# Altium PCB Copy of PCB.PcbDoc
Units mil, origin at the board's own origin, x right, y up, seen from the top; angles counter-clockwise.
Board outline 1574.8 x 1496.06 mil, 2 copper layers (Top Layer, Bottom Layer); 38 components, 67 nets, 271 pads, 68 vias.
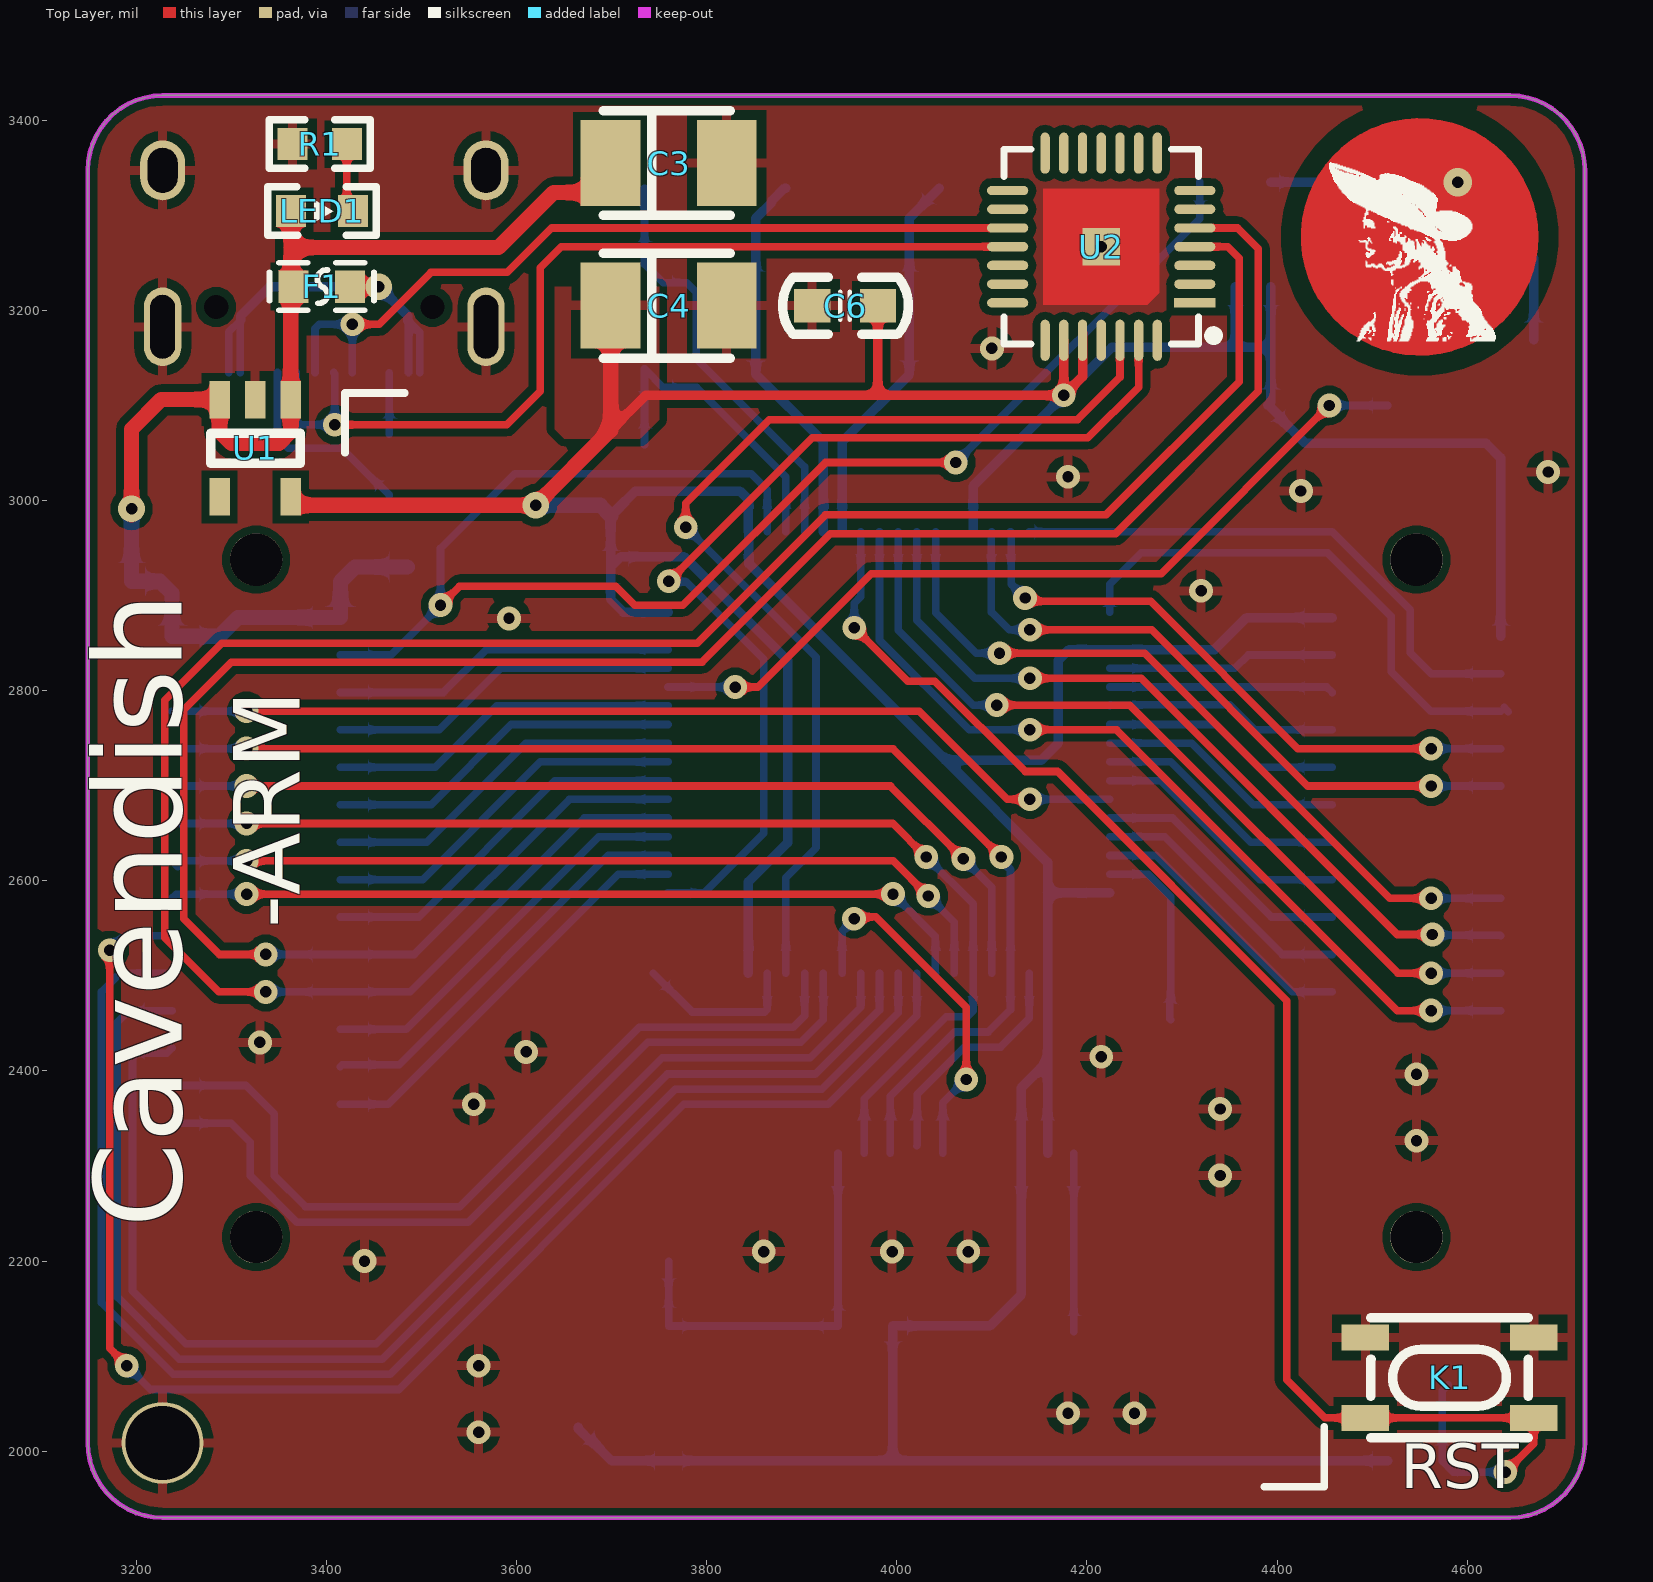
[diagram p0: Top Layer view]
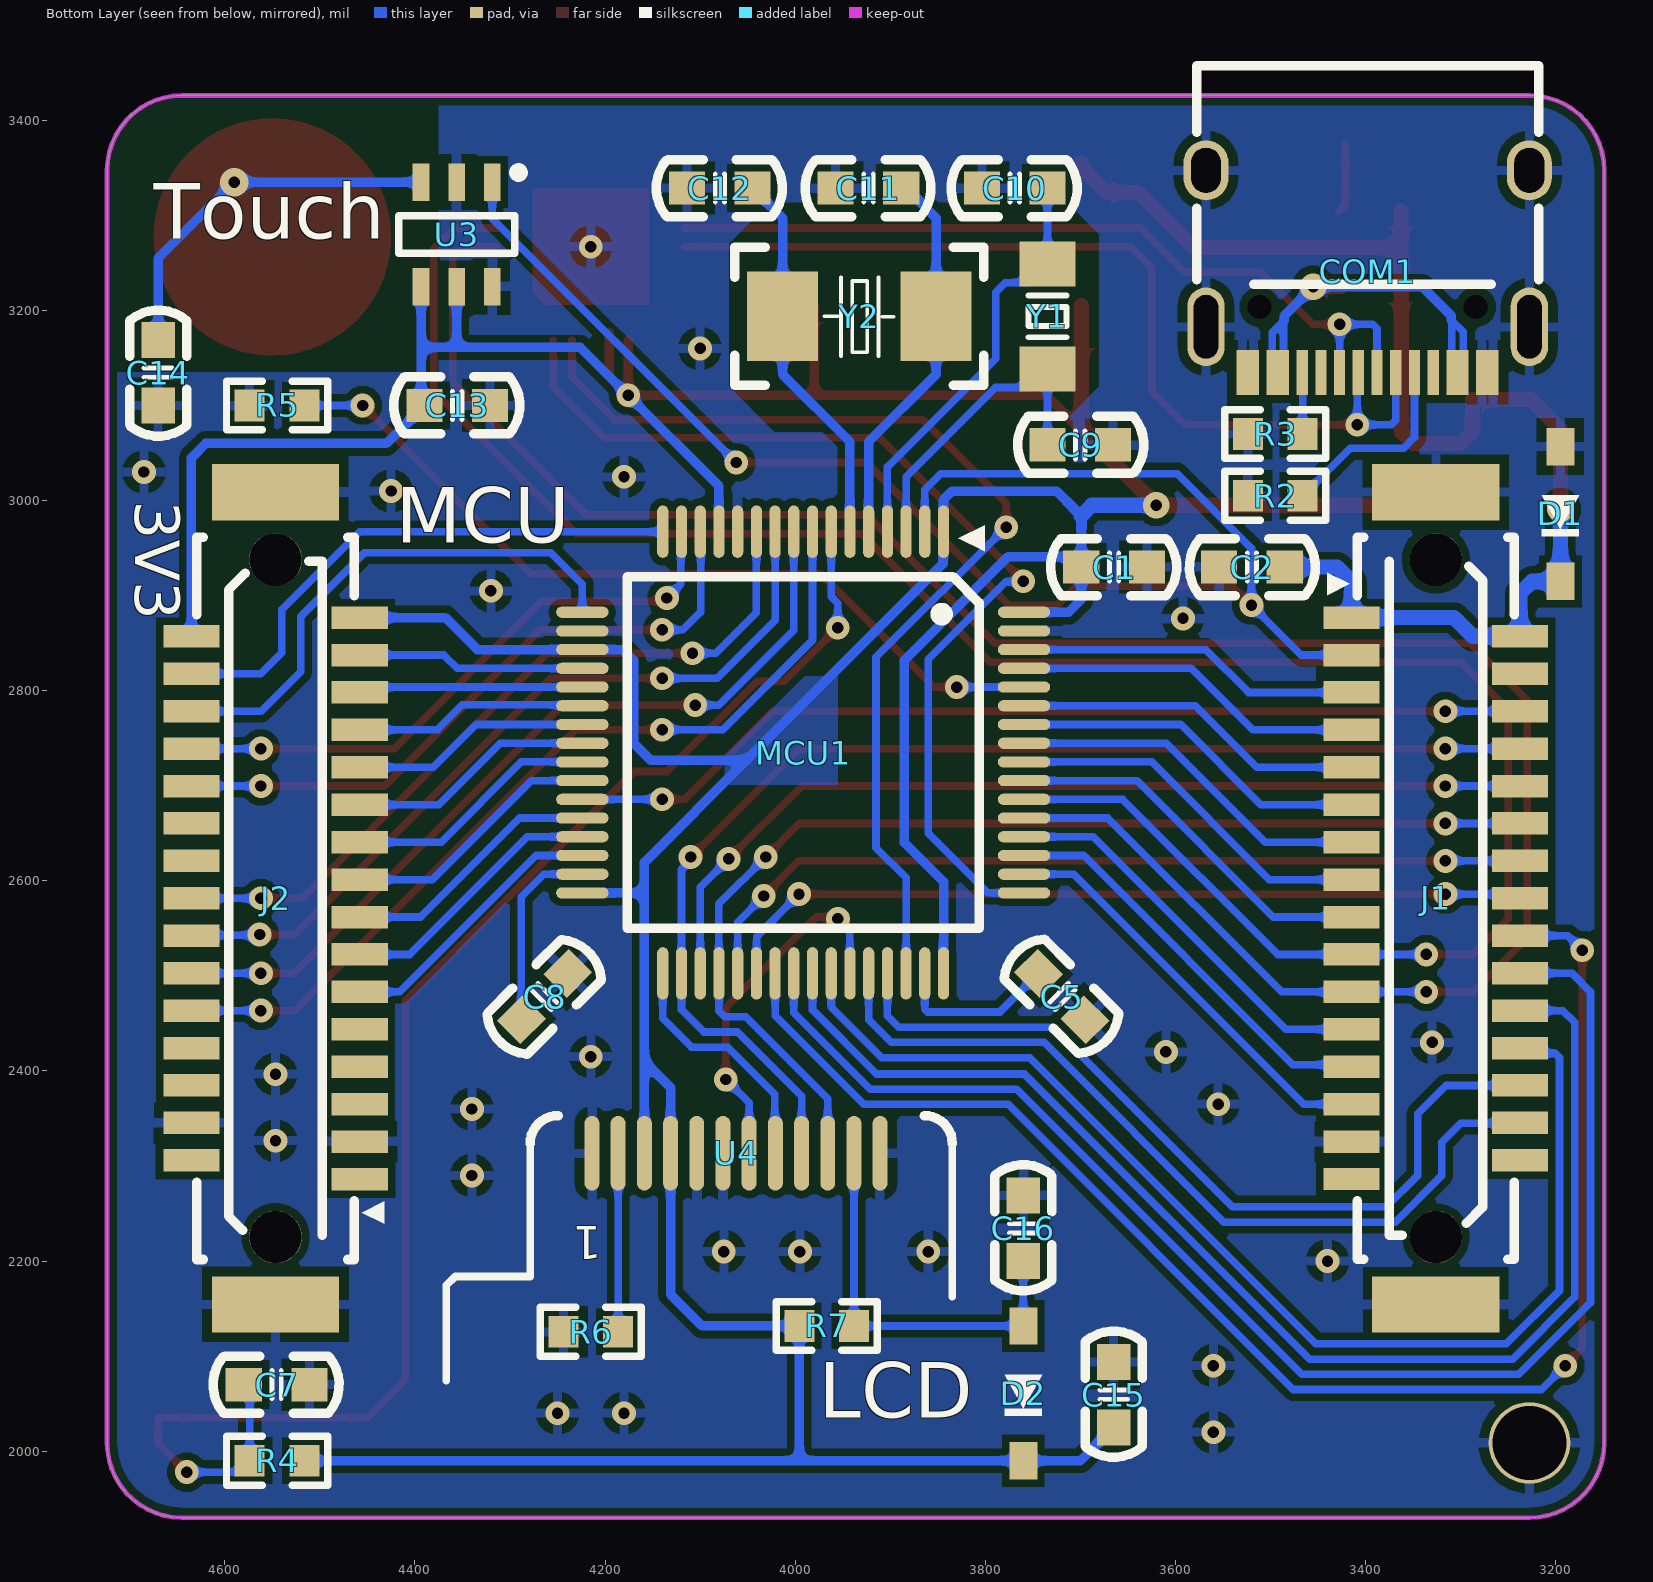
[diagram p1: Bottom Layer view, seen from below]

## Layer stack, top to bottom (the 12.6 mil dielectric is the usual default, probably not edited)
Top Solder: solder mask 0.4, Solder Resist, Dk 3.5
Top Layer: signal copper 1.4
Dielectric 1: dielectric 12.6, FR-4, Dk 4.8
Bottom Layer: signal copper 1.4
Bottom Solder: solder mask 0.4, Solder Resist, Dk 3.5

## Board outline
3148.94,2008.74 ccw(c3227.68,2008.74) 3227.68,1930 4645,1930 ccw(c4645,2008.74) 4723.74,2008.74 4723.74,3347.32 ccw(c4645,3347.32) 4645,3426.06 3260.17,3426.06 3227.68,3426.06 ccw(c3227.68,3347.32) 3148.94,3347.32

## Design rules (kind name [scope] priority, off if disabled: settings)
Clearance [All] p1: gap=8 ignorepadtopadclearanceinfootprint=TRUE
HoleSize [All] p1: absolutevalues=TRUE maxlimit=400 minlimit=1 maxpercent=80.000 minpercent=20.000
HoleToHoleClearance [All] p1: gap=6 allowstackedmicrovias=TRUE
MinimumSolderMaskSliver [All] p1: minsoldermaskwidth=1
PolygonConnect [All] p1: connectstyle=Relief reliefconductorwidth=10 reliefentries=4 polygonreliefangle="90 Angle" airgapwidth=10
RoutingVias [All] p1: holewidth=28 width=50 viastyle="Through Hole" minholewidth=12 minwidth=16 maxholewidth=28 maxwidth=50
SilkToSilkClearance [All] p1: silktosilkclearance=0
SilkToSolderMaskClearance [IsPad] p1: minsilkscreentomaskgap=0 clearancetoexposedcopper=TRUE
SolderMaskExpansion [All] p1: expansion=4 istentingtop=FALSE
Width [All] p1: maxlimit=50 minlimit=8 preferedwidth=10
25 further rules are at their usual default settings.

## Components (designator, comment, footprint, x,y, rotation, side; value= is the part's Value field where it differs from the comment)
C1 "100NF" CAP_0603 3630,2930 r0 bottom
C2 "100NF" CAP_0603 3554,2930 r180 bottom
C3 "22UF" CAP_3528_B 3760,3355 r180 top
C4 "22UF" CAP_3528_B 3760,3205 r180 top
C5 "10UF" CAP_0603 3695.16,2453.83 r45 bottom
C6 "100NF" CAP_0603 3911,3205 r0 top
C7 "100NF" CAP_0603 4511,2070 r0 bottom
C8 "10UF" CAP_0603 4239.22,2502.62 r315 bottom
C9 "10PF" CAP_0603 3734.62,3058.59 r180 bottom
C10 "10PF" CAP_0603 3734.62,3328.63 r0 bottom
C11 "22PF" CAP_0603 3888.37,3328.63 r0 bottom
C12 "22PF" CAP_0603 4044.77,3328.63 r0 bottom
C13 "100NF" CAP_0603 4321,3100 r0 bottom
C14 "22PF" CAP_0603 4670,3169 r270 bottom
C15 "100NF" CAP_0603 3665,2025 r90 bottom
C16 "4.7UF" CAP_0603 3760,2200 r90 bottom
COM1 "Type-C" USB-Type-C_16A 3397.75,3346.33 r0 bottom
D1 "B5819W" DIODE_SOD123 3195,3056.73 r270 bottom
D2 "1N4148" DIODE_SOD123 3760,2131.73 r270 bottom
F1 "FUSE" Fuse_0603 3395,3225 r0 top
J1 "31PIN" BTB-DM3-31P 3326.1,2937.88 r270 bottom
J2 "31PIN" BTB-DM3-31P 4546.57,2225.28 r90 bottom
K1 "KEY" KEY_SMD 4492.84,2119.65 r0 top
LED1 "LED_R/G/B/Y" LED_0603_R 3395.31,3304.4 r180 top
MCU1 "STM32F405RET6" LQFP_64_10X10 3991.59,2734.9 r0 bottom
R1 "10K" RESC_0603_2 3392.99,3375 r0 top
R2 "5.1K" RESC_0603_2 3495,3005 r180 bottom
R3 "5.1K" RESC_0603_2 3495,3070 r180 bottom
R4 "10K" RESC_0603_2 4545,1990 r0 bottom
R5 "10K" RESC_0603_2 4545,3100 r0 bottom
R6 "20R" RESC_0603_2 4214.92,2125.63 r180 bottom
R7 "4.7K" RESC_0603_2 3966.89,2131.73 r180 bottom
U1 "SPX3819M5-L" SOT23_5 3325,3055 r90 top
U2 "CH549F" "QFN28 5x5_L" 4215,3267 r90 top
U3 "TTP223" SOT-23-6 4318.6,3335 r270 bottom
U4 "TFT_1.3_12Pin" LCD_1.3B 4233.74,2333.06 r180 top
Y1 "32KHz" XTAL_SMD_3215 3734.62,3193.61 r270 bottom
Y2 "8MHz" XTAL-SMD5032-2P 3932.53,3193.84 r180 bottom

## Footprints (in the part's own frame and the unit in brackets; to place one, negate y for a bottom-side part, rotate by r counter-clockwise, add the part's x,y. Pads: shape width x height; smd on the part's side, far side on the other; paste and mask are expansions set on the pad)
BTB-DM3-31P [mm]
  rect 0.6x1.5 smd: 1(1.55,-2.25) 2(2.05,2.25) 3(2.55,-2.25) 4(3.05,2.25) 5(3.55,-2.25) 6(4.05,2.25) 7(4.55,-2.25) 8(5.05,2.25) 9(5.55,-2.25) 10(6.05,2.25) 11(6.55,-2.25) 12(7.05,2.25) 13(7.55,-2.25) 14(8.05,2.25) 15(8.55,-2.25) 16(9.05,2.25) 17(9.55,-2.25) 18(10.05,2.25) 19(10.55,-2.25) 20(11.05,2.25) 21(11.55,-2.25) 22(12.05,2.25) 23(12.55,-2.25) 24(13.05,2.25) 25(13.55,-2.25) 26(14.05,2.25) 27(14.55,-2.25) 28(15.05,2.25) 29(15.55,-2.25) 30(16.05,2.25) 31(16.55,-2.25)
  rect 1.5x3.4 smd: 32(19.9,0) 33(-1.8,0)
  round 1.4 hole 1.4 unplated: ""(0,0) ""(18.1,0)
  silkscreen extent -0.6,-2.9 18.7,2.1, body extent -1.51,-2.81 19.59,2.79, height 3.35
CAP_0603 [mil]
  rect 38x35 smd: 1(0,0) 2(69,0)
  silkscreen extent -31,-30 101,30, body extent 4,-16 67,16, height 12
CAP_3528_B [mm]
  rect 1.6x2.3 smd: 1(1.55,0) 2(-1.55,0)
  silkscreen extent -1.65,-1.4 1.75,1.4, body extent -1.75,-1.4 1.75,1.4, height 1.9
DIODE_SOD123 [mm]
  rect 1x0.75 smd: 1(0,0) 2(3.6,0)
  silkscreen extent 1.3,-0.5 2.4,0.5, body extent -0.05,-0.8 3.65,0.8, height 1.27
Fuse_0603 [mil]
  rect 31.8x34 smd mask+2: 1(-29.7,0) 2(29.7,0)
  silkscreen extent -55,-25 55,25, body extent -33,-18 34,18, height 30
KEY_SMD [mm] "3*4*2.5MM"
  rect 1.27x0.7 smd: 1(0,0) 1(4.5,0) 2(0,-2.15) 2(4.5,-2.15)
  silkscreen extent 0.15,-2.68 4.35,0.52, body extent -0.1,-2.67 4.6,0.53, height 2.51
LCD_1.3B [mm]
  oval 0.4x2 smd far side: 1(0.508,0.5) 2(1.208,0.5) 3(1.908,0.5) 4(2.608,0.5) 5(3.308,0.5) 6(4.008,0.5) 7(4.708,0.5) 8(5.408,0.5) 9(6.108,0.5) 10(6.808,0.5) 11(7.508,0.5) 12(8.208,0.5)
  silkscreen extent -5.48,-19.81 20.68,9.41, body extent -5.48,-19.81 20.68,9.41, height 1
LED_0603_R [mm]
  rect 0.8x0.85 smd: 1(-0.832,0) 2(0.832,0)
  silkscreen extent -1.45,-0.65 1.45,0.65, body extent -0.81,-0.4 0.81,0.4, height 0.6
LQFP_64_10X10 [mm]
  oval 0.3x1.4 smd: 1(-3.75,-5.9) 2(-3.25,-5.9) 3(-2.75,-5.9) 4(-2.25,-5.9) 5(-1.75,-5.9) 6(-1.25,-5.9) 7(-0.75,-5.9) 8(-0.25,-5.9) 9(0.25,-5.9) 10(0.75,-5.9) 11(1.25,-5.9) 12(1.75,-5.9) 13(2.25,-5.9) 14(2.75,-5.9) 15(3.25,-5.9) 16(3.75,-5.9) 33(3.75,5.9) 34(3.25,5.9) 35(2.75,5.9) 36(2.25,5.9) 37(1.75,5.9) 38(1.25,5.9) 39(0.75,5.9) 40(0.25,5.9) 41(-0.25,5.9) 42(-0.75,5.9) 43(-1.25,5.9) 44(-1.75,5.9) 45(-2.25,5.9) 46(-2.75,5.9) 47(-3.25,5.9) 48(-3.75,5.9)
  oval 1.4x0.3 smd: 17(5.9,-3.75) 18(5.9,-3.25) 19(5.9,-2.75) 20(5.9,-2.25) 21(5.9,-1.75) 22(5.9,-1.25) 23(5.9,-0.75) 24(5.9,-0.25) 25(5.9,0.25) 26(5.9,0.75) 27(5.9,1.25) 28(5.9,1.75) 29(5.9,2.25) 30(5.9,2.75) 31(5.9,3.25) 32(5.9,3.75) 49(-5.9,3.75) 50(-5.9,3.25) 51(-5.9,2.75) 52(-5.9,2.25) 53(-5.9,1.75) 54(-5.9,1.25) 55(-5.9,0.75) 56(-5.9,0.25) 57(-5.9,-0.25) 58(-5.9,-0.75) 59(-5.9,-1.25) 60(-5.9,-1.75) 61(-5.9,-2.25) 62(-5.9,-2.75) 63(-5.9,-3.25) 64(-5.9,-3.75)
  silkscreen extent -4.85,-6.08 4.7,4.7, body extent -6.07,-6.07 6.07,6.07, height 1.62
"QFN28 5x5_L" [mm] "28脚，长x宽x高：5x5x0.8mm，脚距：0.5mm"
  rect 0.25x1.1 smd: 1(-1.5,-2.5)
  oval 0.25x1.1 smd: 2(-1,-2.5) 3(-0.5,-2.5) 4(0,-2.5) 5(0.5,-2.5) 6(1,-2.5) 7(1.5,-2.5) 15(1.5,2.5) 16(1,2.5) 17(0.5,2.5) 18(0,2.5) 19(-0.5,2.5) 20(-1,2.5) 21(-1.5,2.5)
  oval 1.1x0.25 smd: 8(2.5,-1.5) 9(2.5,-1) 10(2.5,-0.5) 11(2.5,0) 12(2.5,0.5) 13(2.5,1) 14(2.5,1.5) 22(-2.5,1.5) 23(-2.5,1) 24(-2.5,0.5) 25(-2.5,0) 26(-2.5,-0.5) 27(-2.5,-1) 28(-2.5,-1.5)
  rect 1x1 smd: 29(0,0)
  Top Layer region: -1.55,1.55 1.55,1.55 1.55,-1.55 -1.225,-1.55 -1.55,-1.225
  silkscreen extent -2.6,-3.13 2.6,2.6, body extent -2.51,-2.51 2.51,2.51, height 0.75
RESC_0603_2 [mm]
  rect 0.8x0.85 smd: 1(-0.73,0) 2(0.73,0)
  silkscreen extent -1.35,-0.65 1.35,0.65, body extent -0.8,-0.4 0.8,0.4, height 0.38
SOT23_5 [mm]
  rect 1x0.55 smd: 1(1.3,-0.95) 2(1.3,0) 3(1.3,0.95) 4(-1.3,0.95) 5(-1.3,-0.95)
  silkscreen extent -0.4,-1.21 0.4,1.19, body extent -1.52,-1.51 1.48,1.49, height 1.3
SOT-23-6 [mm]
  rect 1x0.45 smd: 1(0,0) 2(0,-0.95) 3(0,-1.9) 4(2.794,-1.9) 5(2.794,-0.95) 6(2.794,0)
  silkscreen extent -0.38,-2.5 1.91,0.82, body extent -0.01,-2.45 2.8,0.55, height 1.15
USB-Type-C_16A [mm]
  round 0 hole 0.65: 0(-2.89,3.625) 0(2.89,3.625)
  oval 1.2x1.6 hole 0.8 slot 1.2 at 90 deg: 1(-4.32,-0.025) 1(4.32,-0.025)
  oval 1x2.1 hole 0.66 slot 1.7 at 90 deg: 1(-4.32,4.155) 1(4.32,4.155)
  rect 0.3x1.2 smd: A1(-3.35,5.375) A4(-2.55,5.375) A5(-1.25,5.375) A6(-0.25,5.375) A7(0.25,5.375) A8(-1.75,5.375) A9(2.55,5.375) A12(3.35,5.375) B1(3.05,5.375) B4(2.25,5.375) B5(1.75,5.375) B6(0.75,5.375) B7(-0.75,5.375) B8(1.25,5.375) B9(-2.25,5.375) B12(-3.05,5.375)
  silkscreen extent -4.57,-2.82 4.57,3.02, body extent -4.47,-2.63 4.47,5.27, height 3.25
XTAL-SMD5032-2P [mil]
  rect 74.8x94.5 smd mask+2: 1(-80.7,0) 2(80.7,0)
  silkscreen extent -131,-73 131,73, body extent -98,-63 99,63, height 39
XTAL_SMD_3215 [mm]
  rect 1.2x1.5 smd: 1(-1.4,0) 2(1.4,0)
  silkscreen extent -0.56,-0.51 0.56,0.51, body extent -1.61,-0.76 1.61,0.76, height 0.91

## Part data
C1 C2 C5 C6 C7 C8 C9 C10 C11 C12 C13 C14 C15 C16: library part CAP, "CAP  12~50V"
C3 C4: library part CAP_TA, "CAP  6~12V  钽电容"
COM1: library part USB-type_c, "USB"
D1 D2: library part Diode-SM, "Diode_肖特基/二极管"
J1 J2: library part BTB_DF3_31Pin, "BTB"
K1: "Key"
LED1: library part LED_SMT, "LED"
MCU1: library part STM32f4_R, "MCU"
R1 R4 R5 R6 R7: library part RES_S, "RES 贴片"
R2 R3: library part RES, "RES 贴片"
U1: "DC-DC   3.3V  500ma"
U2: "MCU", External Clock Frequency Rang=6MHz~25MHz, JLCPCB Part Class="Extended Part", Manufacturer=WCH(南京沁恒), Maximum Frequency=48MHz, Operating Temperature Range=-40~+70, Supply Voltage Range=3.3V~5V
U3: "触摸芯片"
U4: library part "LCD_1.3   T", "ST7789V-SPI"
Y1 Y2: library part XTAL, "CRYSTAL"

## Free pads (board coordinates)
  round 86 hole 78: 0(3227.68,2008.74)

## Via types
v1: diameter 25, hole 12, Top Layer to Bottom Layer, tented both sides, 64 vias
v2: diameter 28, hole 12, Top Layer to Bottom Layer, tented both sides, 3 vias
v3: diameter 30, hole 12, Top Layer to Bottom Layer, tented both sides, 1 vias

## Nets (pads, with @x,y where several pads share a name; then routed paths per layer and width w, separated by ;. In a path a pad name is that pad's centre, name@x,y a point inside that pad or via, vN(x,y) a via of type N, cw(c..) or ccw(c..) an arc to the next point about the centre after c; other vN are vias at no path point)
+5: C2.2 C3.1 D1.2 F1.1 J1.1 J1.2 LED1.2 U1.1 U1.3 | length 1392.4
  Top Layer w16: v2@3195,2985 v2(3195,2991.22) 3195,3075 3226.18,3106.18 U1.3 3287.6,3072.4 3300,3060 3350,3060 3362.4,3072.4 U1.1 F1.1@3362.4,3225 ; LED1.2 3362.57,3266.07 ; F1.1 3362.57,3227.73 3362.57,3266.07 ; C3.1 3698.98,3350.51 3672.48,3324.02 3639.02,3324.02 3581.07,3266.07 3362.57,3266.07
  Bottom Layer w16: v2(3195,2991.22) D1.2 3225,2915 3237.52,2902.48 J1.2 3287.17,2857.17 3306.86,2876.86 J1.1 3414.69,2914.69 3430,2930 C2.2
BOOT0: MCU1.60 R5.1 | length 879.6
  Top Layer w8: v1(3830,2803.8) 3853.8,2803.8 3973,2923 4278,2923 v1(4455,3100)
  Bottom Layer w8: MCU1.60 v1(3830,2803.8) ; v1(4455,3100) R5.1
BOOT1: J2.15 MCU1.28 | length 277.2
  Bottom Layer w8: MCU1.28 4290,2666 4394.11,2561.89 J2.15
CAN_RX: J1.28 MCU1.44 | length 885.9
  Bottom Layer w8: J1.28 3237.88,2345 3300,2345 3320,2325 3320,2290 3369,2241 3549,2241 3738,2430 3899,2430 3922.69,2453.69 MCU1.44
CAN_TX: J1.26 MCU1.45 | length 884.2
  Bottom Layer w8: J1.26 3315.27,2384.73 3345,2355 3345,2290 3378,2257 3540.05,2257 3729.05,2446 3890.81,2446 3903,2458.19 MCU1.45
CC1: COM1.A5 R2.2 | length 212
  Bottom Layer w8: COM1.A5 3348.54,3066.46 3360,3055 3416.26,3055 3453.53,3017.73 3454.51,3017.73 3466.26,3005.98 R2.2
CC2: COM1.B5 R3.2 | length 64.3
  Bottom Layer w8: R3.2 COM1.B5@3466.26,3134.33
CH_RXD: J1.21 MCU1.53 U2.4 | length 2328.9
  Top Layer w8: v1(3336.21,2483.15) 3286.85,2483.15 3230,2540 3230,2790 3290,2850 3790,2850 3925,2985 4220,2985 4360,3125 4360,3255 4348,3267 U2.4
  Bottom Layer w8: v1(3336.21,2483.15) J1.21 3488.15,2483.15 3671,2666 MCU1.53
CH_TXD: J1.19 MCU1.54 U2.5 | length 2306.7
  Top Layer w8: v1(3336.21,2522.53) 3287.47,2522.53 3250,2560 3250,2780 3300,2830 3795,2830 3930,2965 4230,2965 4380,3115 4380,3265 4358.31,3286.68 U2.5
  Bottom Layer w8: v1(3336.21,2522.53) J1.19 3492.53,2522.53 3655.69,2685.69 MCU1.54
D+: COM1.A6 COM1.B6 U2.17 | length 869.1
  Top Layer w8: v1(3427.28,3185.31) 3455.31,3185.31 3510,3240 3590.31,3240 3637,3286.69 U2.17
  Bottom Layer w8: COM1.A6 3387.91,3180.63 3392.6,3185.31 v1(3427.28,3185.31) COM1.B6
D-: COM1.A7 COM1.B7 U2.18 | length 1009.9
  Top Layer w8: v1(3408.78,3079.69) 3589.69,3079.69 3625,3115 3625,3245 3647,3267 U2.18
  Bottom Layer w8: COM1.B7 3368.23,3084.37 3372.91,3079.69 v1(3408.78,3079.69) 3408.78,3133.53 COM1.A7
D/C: MCU1.43 U4.7 | length 384.6
  Top Layer w8: v1(3955,2560) 3957,2562 3978,2562 4073,2467 v1(4073,2391)
  Bottom Layer w8: MCU1.43 3942.37,2546.81 3955,2559.44 v1(3955,2560) ; U4.7 4048.39,2366.39 v1(4073,2391)
DAC_OUT1: J2.29 MCU1.20 | length 239.9
  Bottom Layer w8: MCU1.20 4355.48,2823.48 4369.48,2837.48 J2.29
DAC_OUT2: J2.27 MCU1.21 | length 236.5
  Bottom Layer w8: MCU1.21 4452.3,2803.8 J2.27
DIR: J2.21 MCU1.24 | length 260.9
  Bottom Layer w8: MCU1.24 4310.26,2744.74 4375,2680 J2.21
GND: C1.1 C2.1 C3.2 C4.2 C5.1 C6.1 C7.1 C8.1 C9.2 C10.2 C11.2 C12.2 C13.1 C14.2 C15.2 C16.2 COM1.1 COM1.A1 COM1.A12 COM1.B1 COM1.B12 D1.1 J1.29 J1.32 J1.33 J2.3 J2.4 J2.32 J2.33 K1.1 MCU1.12 MCU1.18 MCU1.63 pad.0 R1.1 R2.1 R3.1 R5.2 R6.1 U1.2 U2.29 U3.2 U3.6 U4.1 U4.5 U4.6 U4.12
  other v1: 3560,2020 4180,2040 4250,2040 3560,2090 3440,2200 3860,2210 3995,2210 4075,2210 4340,2290 4546.57,2326.57 4340,2360 3555,2365 4546.57,2396.57 4215,2415 3610,2420 3330,2430 3592,2876 4320,2905 4425,3010 4180,3025 4685,3030 4100,3160 4215,3267
GPIO0: J2.10 MCU1.8 | length 928.8
  Top Layer w8: v1(4140,2759) 4231,2759 4526.54,2463.46 v1(4562,2463.46)
  Bottom Layer w8: MCU1.8 3981.74,2853.26 4076,2759 v1(4140,2759) ; v1(4562,2463.46) J2.10
GPIO1: J2.12 MCU1.9 | length 886.8
  Top Layer w8: v1(4105.18,2784.82) 4245.18,2784.82 4527.17,2502.83 v1(4562,2502.83)
  Bottom Layer w8: MCU1.9 4001.43,2863.57 4080.18,2784.82 v1(4105.18,2784.82) ; v1(4562,2502.83) J2.12
GPIO2: J2.14 MCU1.10 | length 844.7
  Top Layer w8: v1(4140,2813) 4257,2813 4526.49,2543.51 v1(4563.31,2543.51)
  Bottom Layer w8: MCU1.10 4021.11,2873.89 4082,2813 v1(4140,2813) ; v1(4563.31,2543.51) 4563.96,2542.86 4634.5,2542.86 J2.14
GPIO3: J2.16 MCU1.11 | length 803.9
  Top Layer w8: v1(4108,2839.46) 4260.54,2839.46 4518.43,2581.57 v1(4562,2581.57)
  Bottom Layer w8: MCU1.11 4040.8,2882.2 4083.54,2839.46 v1(4108,2839.46) ; v1(4562,2581.57) J2.16
GPIOA: J1.15 MCU1.56 | length 395.9
  Bottom Layer w8: J1.15 3501.27,2601.27 3625.06,2725.06 MCU1.56
GPIOB: J1.13 MCU1.57 | length 387.7
  Bottom Layer w8: J1.13 3505.64,2640.64 3609.74,2744.74 MCU1.57
MISO_2: J1.10 MCU1.35 | length 997
  Top Layer w8: v1(3316,2699.69) 3993.31,2699.69 v1(4070,2623)
  Bottom Layer w8: J1.10 v1(3316,2699.69) ; v1(4070,2623) 4099.85,2593.15 MCU1.35
MOSI_2: J1.12 MCU1.36 U4.10 | length 1200.4
  Top Layer w8: v1(3316,2660.32) 3995.68,2660.32 v1(4031,2625)
  Bottom Layer w8: J1.12 v1(3316,2660.32) ; U4.10 3965.71,2370.71 4052,2457 4074,2457 4080.17,2463.17 MCU1.36 4080.17,2575.83 v1(4031,2625)
NetC5_2: C5.2 MCU1.47 | length 175.4
  Bottom Layer w8: C5.2 3784.56,2462 3860.74,2462 3863.63,2464.89 MCU1.47
NetC8_2: C8.2 MCU1.31 | length 204.2
  Bottom Layer w8: MCU1.31 4264.25,2606.95 4288.01,2583.19 4288.01,2475.04 4286.95,2473.98 4286.95,2454.89 C8.2
NetLED1_1: LED1.1 R1.2 | length 73
  Top Layer w8: R1.2@3421.44,3374.7 3421.44,3311.01 LED1.1
NetR6_2: R6.2 U4.2 | length 187.7
  Bottom Layer w8: R6.2 U4.2
NRST: C7.2 K1.2 MCU1.7 R4.2 | length 1620.1
  Top Layer w8: v1(3955.15,2866.15) 4011.3,2810 4040,2810 4135,2715 4169,2715 4410,2474 4410,2075 4450,2035 4492.83,2035 4670,2035 4670,2008 v1(4640,1978)
  Bottom Layer w8: v1(3955.15,2866.15) 3955.15,2892.15 3962.06,2899.06 MCU1.7 ; C7.2 4573.74,2063.74 4573.74,1989.75 4585.49,1978 v1(4640,1978)
NSS_2: MCU1.33 U4.8 | length 252.5
  Bottom Layer w8: U4.8@4020.83,2321.38 4021.4,2321.95 4021.4,2375.4 4071,2425 4109,2425 4139.22,2455.22 MCU1.33
NSS_2_2: J1.6 MCU1.27 | length 1024.8
  Top Layer w8: v1(3316,2778.43) 4023.57,2778.43 4116.31,2685.69 v1(4140,2685.69)
  Bottom Layer w8: J1.6 v1(3316,2778.43) ; v1(4140,2685.69) MCU1.27
NSS_2_3: J2.17 MCU1.26 | length 277.2
  Bottom Layer w8: MCU1.26 4277.63,2705.37 4381.74,2601.26 J2.17
PC10: J1.25 MCU1.51 | length 436.7
  Bottom Layer w8: J1.25 3416.8,2406.53 3476.53,2406.53 3696.63,2626.63 MCU1.51
PC11: J1.23 MCU1.52 | length 428.5
  Bottom Layer w8: J1.23 3483.78,2443.78 3686.32,2646.32 MCU1.52
PC13: J1.3 MCU1.2 U3.1 | length 1636.1
  Top Layer w8: v1(3520,2890) 3540,2910 3704.42,2910 3724.42,2890 3775,2890 3925,3040 v1(4062,3040)
  Bottom Layer w8: J1.3 3467.49,2837.49 v1(3520,2890) 3520,2950 3598.09,3028.09 3846.91,3028.09 3863.63,3011.37 MCU1.2 ; v1(4062,3040) 4318.6,3296.6 U3.1
RES: C16.1 D2.1 R7.2 U4.11 | length 428.1
  Bottom Layer w8: C16.1 D2.1 R7.2 U4.11
SCK_2: J1.8 MCU1.34 U4.9 | length 1308.1
  Top Layer w8: v1(3316,2739.06) 3995.94,2739.06 v1(4110,2625)
  Bottom Layer w8: J1.8 v1(3316,2739.06) ; U4.9 3993.27,2373.27 4061,2441 4096,2441 4119.54,2464.54 MCU1.34 4119.54,2611.81 4110,2621.35 v1(4110,2625)
SCL_2: J2.13 MCU1.29 | length 285.4
  Bottom Layer w8: MCU1.29 4281.68,2646.32 4405.48,2522.52 J2.13
SDA_2: J2.11 MCU1.30 | length 293.6
  Bottom Layer w8: MCU1.30 4272.37,2626.63 4415.85,2483.15 J2.11
STEP: J2.19 MCU1.25 | length 269.1
  Bottom Layer w8: MCU1.25 4287.94,2725.06 4372.37,2640.63 J2.19
SWCLK: MCU1.49 U2.27 | length 1071.8
  Top Layer w8: v1(3760,2915) 3911,3066 4201,3066 4254.37,3119.37 U2.27
  Bottom Layer w8: MCU1.49 3797.26,2587.26 3860,2650 3860,2832.93 3778.29,2914.64 3760.36,2914.64 v1(3760,2915)
SWDIO: MCU1.46 U2.26 | length 1114.8
  Top Layer w8: v1(3778,2972) 3778,2997 3866,3085 4190,3085 4234.69,3129.69 U2.26
  Bottom Layer w8: v1(3778,2972) 3915,2835 3915,2635 3883.32,2603.32 MCU1.46
TM1_CH1: J1.22 MCU1.41 | length 1370.9
  Bottom Layer w8: J1.22 3192.47,2463.47 3180,2451 3180,2162.26 3245.37,2096.89 3458.89,2096.89 3758.75,2396.75 3914.38,2396.75 3981.74,2464.12 MCU1.41
TM1_CH2: J1.24 MCU1.42 | length 1262.3
  Bottom Layer w8: J1.24 3232.06,2418.63 3200.68,2418.63 3196,2413.95 3196,2168.89 3251.99,2112.89 3452.26,2112.89 3753.37,2414 3909,2414 3962.06,2467.06 MCU1.42
TM2_CH1: J1.27 MCU1.50 | length 444.8
  Bottom Layer w8: J1.27 3465.04,2365.04 3706.95,2606.95 MCU1.50
TM2_CH2: J1.17 MCU1.55 | length 404
  Bottom Layer w8: J1.17 3496.9,2561.9 3640.37,2705.37 MCU1.55
TM3_CH1: J2.25 MCU1.22 | length 245.5
  Bottom Layer w8: MCU1.22 4224.11,2784.11 4225,2785 4225.16,2784.84 4248.95,2784.84 4249.11,2785 4350,2785 4376.26,2758.74 J2.25
TM3_CH2: J2.23 MCU1.23 | length 252.8
  Bottom Layer w8: MCU1.23 4335.57,2764.43 4380.63,2719.37 J2.23
TM4_CH1: J1.11 MCU1.58 | length 379.6
  Bottom Layer w8: J1.11 3510.01,2680.01 3594.43,2764.43 MCU1.58
TM4_CH2: J1.9 MCU1.59 | length 371.4
  Bottom Layer w8: J1.9 3514.38,2719.38 3579.11,2784.11 MCU1.59
TM4_CH3: J1.7 MCU1.61 | length 371.4
  Bottom Layer w8: J1.7 3518.75,2758.75 3583.48,2823.48 MCU1.61
TM4_CH4: J1.5 MCU1.62 | length 363.3
  Bottom Layer w8: J1.5 3523.12,2798.12 3568.17,2843.17 MCU1.62
TM5_CH1: J2.22 MCU1.14 | length 696.4
  Top Layer w8: v1(4140,2863.96) 4268.04,2863.96 4432.32,2699.68 v1(4562,2699.68)
  Bottom Layer w8: MCU1.14 4099.21,2966.54 4099.21,2882.79 4118.04,2863.96 v1(4140,2863.96) ; v1(4562,2699.68) J2.22
TM5_CH2: J2.24 MCU1.15 | length 636
  Top Layer w8: v1@4139.91,2892.5 4141.32,2893.91 4267.09,2893.91 4421.95,2739.05 v1(4562,2739.05)
  Bottom Layer w8: MCU1.15 4120.27,2966.45 4120.27,2912.14 v1(4134.91,2897.5) ; v1(4562,2739.05) J2.24
TM8_CH1: J1.14 MCU1.37 | length 912
  Top Layer w8: v1(3316,2620.95) 3996.05,2620.95 v1(4033,2584)
  Bottom Layer w8: J1.14@3243.47,2615 J1.14 v1(3316,2620.95) ; v1(4033,2584) 4060.48,2556.52 MCU1.37
TM8_CH2: J1.16 MCU1.38 | length 862.2
  Top Layer w8: v1(3316,2586) v1(3996,2586)
  Bottom Layer w8: J1.16 3241.94,2586 v1(3316,2586) ; v1(3996,2586) 4040.6,2541.4 4040.6,2502.81 MCU1.38
TM8_CH3: J1.18 MCU1.39 | length 1565.1
  Top Layer w8: v1(3172,2527) 3172,2108.19 3190,2090.19 v1(3190,2090)
  Bottom Layer w8: v1(3172,2527) 3187.21,2542.21 J1.18 ; v1(3190,2090) 3215.11,2064.89 3475.89,2064.89 3775.75,2364.75 3927.63,2364.75 4021.11,2458.23 MCU1.39
TM8_CH4: J1.20 MCU1.40 | length 1477.5
  Bottom Layer w8: J1.20 3182.84,2502.84 3163.44,2483.44 3163.44,2156.19 3238.74,2080.89 3466.89,2080.89 3766.75,2380.75 3921,2380.75 4001.43,2461.17 MCU1.40
Touch: C14.1 U3.3 | length 1149.7
  Top Layer w10: 4670,3277.32 ccw(c4550,3277.32) 4670,3277.32
  Bottom Layer w10: U3.3 v3(4590,3335) 4670,3255 C14.1
UART-RXD2: J2.26 MCU1.17 | length 563.4
  Bottom Layer w8: MCU1.17 4223.87,2911.87 4257,2945 4453,2945 4520,2878 4520,2820 4561.58,2778.42 J2.26 ; J2.26@4639,2782.27 J2.26@4643.28,2778
UART-TXD2: J2.28 MCU1.16 | length 584.2
  Bottom Layer w8: MCU1.16 4457.82,2967.18 4540,2885 4540,2840 4562.21,2817.79 J2.28
VBUS: COM1.A4 COM1.A9 COM1.B4 COM1.B9 F1.2 | length 468.6
  Top Layer w16: F1.2 v2(3455,3225)
  Bottom Layer w8: COM1.A4 3297.36,3177.36 3309.17,3189.17 COM1.B9 ; COM1.B4 3486.34,3188.66 3498.15,3176.85 COM1.A9
  Bottom Layer w10: 3309.78,3189.78 3309.78,3194.27 3340.51,3225 v2(3455,3225) 3485.73,3194.27 3485.73,3189.27 3486.34,3188.66
VDD: C1.2 C4.1 C6.2 C13.2 C15.1 D2.2 J2.30 J2.31 MCU1.1 MCU1.13 MCU1.19 MCU1.32 MCU1.48 MCU1.64 R4.1 R7.1 U1.5 U2.23 U2.24 U3.4 U3.5 U4.3 U4.4 | length 6091.7
  Top Layer w10: 3698.98,3073.98 3735.63,3110.63 3980,3110.63 ; C6.2 3980,3110.63 ; U2.23 v1(4175.63,3110.63) ; U2.24@4195.31,3176.57 U2.24 4195.31,3130.32 v1(4175.63,3110.63) ; 3980,3110.63 v1(4175.63,3110.63)
  Top Layer w16: U1.5 3362.4,2995.83 3363.23,2995 v2(3620,2995) 3698.98,3073.98 C4.1
  Bottom Layer w10: C15.1 3665,2023.5 3677.5,2011 3679,2011 3700,1990 3995.63,1990 ; MCU1.64 3712.46,2882.54 3699,2896 C1.2 ; MCU1.48 3843.95,2598.95 3885,2640 3885,2831.97 3775.97,2941 3710,2941 C1.2 ; MCU1.13 4080.17,3015.17 v1(4175.63,3110.63) 4226,3161 4356,3161 ; U4.3 4158.62,2410 ; MCU1.32 4158.62,2587.26 ; U3.5 4356,3161 ; U3.4 4393.4,3161 ; J2.31 4367.85,2876.85 4334.17,2843.17 MCU1.19 4181.17,2843.17 4170,2832 4170,2745 4152,2727 4051,2727 ; R4.1 3995.63,1990 ; J2.30 4635.15,3044.85 4620,3060 4430,3060 4404,3086 4404,3087.5 4391.5,3100 C13.2 4393.4,3103.4 4393.4,3161 ; C1.2 3699,2984 3725,3010 3835,3010 3843.95,3001.05 MCU1.1 3844.29,2966.84 3844.29,2933.71 4051,2727 ; 3995.63,1990 R7.1 4097.8,2131.73 4131.06,2165 U4.4 4131.06,2382.44 4158.62,2410 ; 4051,2727 4158.62,2619.38 4158.62,2587.26 ; 4158.62,2410 4158.62,2587.26 ; 4356,3161 4393.4,3161
  Bottom Layer w16: v2(3620,2995) 3688,2995 3699,2984
XTALA: C11.1 MCU1.5 Y2.2 | length 404.7
  Bottom Layer w10: C11.1@3883.37,3328.63 3881.87,3328.63 3868.37,3315.13 3868.37,3313.63 3851.83,3297.09 Y2.2 3851.83,3132.65 3922.69,3061.8 MCU1.5
XTALB: C12.1 MCU1.6 Y2.1 | length 403.9
  Bottom Layer w10: MCU1.6 3942.37,3061.8 4013.23,3132.65 Y2.1 4013.23,3297.09 C12.1
XTALC: C9.1 MCU1.3 Y1.2 | length 333.4
  Bottom Layer w8: C9.1 Y1.2 3754.24,3118.87 3789.36,3118.87 3883.32,3024.91 MCU1.3
XTALD: C10.1 MCU1.4 Y1.1 | length 511
  Bottom Layer w8: C10.1@3734.62,3314 Y1.1 ; C10.1 Y1.1 ; MCU1.4 3903,3035.22 3789,3149.22 3789,3219.22 3779.12,3229.1 3754.24,3229.1 Y1.1
pads on no net: COM1.0 COM1.A8 COM1.B8 J1. J1.4 J1.30 J1.31 J2. J2.1 J2.2 J2.5 J2.6 J2.7 J2.8 J2.9 J2.18 J2.20 U1.4 U2.1 U2.2 U2.3 U2.6 U2.7 U2.8 U2.9 U2.10 U2.11 U2.12 U2.13 U2.14 U2.15 U2.16 U2.19 U2.20 U2.21 U2.22 U2.25 U2.28

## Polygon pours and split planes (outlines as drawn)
GND on Bottom Layer "GND_L02_P003" (solid, remove dead copper, pour order 3): 3088.18,3541.31 4958.26,3541.31 4958.26,1868.08 3088.18,1868.08
VDD on Bottom Layer "VDD_L02_P000" (solid, remove dead copper, pour order 0): 3955,2815 3955,2701 4074,2701 4074,2731 3990,2815
VDD on Top Layer "VDD_L01_P001" (solid, remove dead copper, pour order 1): 3640,3225 3750,3225 3750,3085 3730,3065 3650,3065 3640,3075
GND on Top Layer "GND_L01_P004" (solid, remove dead copper, pour order 4): 3051.18,3543.31 4921.26,3543.31 4921.26,1870.08 3051.18,1870.08

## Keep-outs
Keep-Out Layer:
  the board outline again, w5

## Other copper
Top Layer:
  pour cut-out: 4404,3277.32 ccw(c4550,3277.32) 4550,3131.32 ccw(c4550,3277.32) 4696,3277.32 ccw(c4550,3277.32) 4550,3423.32 ccw(c4550,3277.32)
  region net Touch: 4430,3277.32 ccw(c4550,3277.32) 4550,3157.32 ccw(c4550,3277.32) 4670,3277.32 ccw(c4550,3277.32) 4550,3397.32 ccw(c4550,3277.32)
  pour cut-out: 3370,3215 3410,3215 3410,3173.8 3409.9,3173.7 3371.3,3173.7 3370,3175
  pour cut-out: 4025,2740 4085,2740 4120,2705 4120,2620 4036,2620 4031,2625
Bottom Layer:
  pour cut-out: 4375,3425.2 4744.09,3425.2 4744.09,3135 4375,3135
  pour cut-out: 3680,3280 3713.63,3313.63 4026.37,3313.63 4070,3270 4070,3120 4022,3072 3728,3072 3680,3120

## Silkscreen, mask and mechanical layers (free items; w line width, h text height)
Top Overlay:
  drawing of 789 lines, arcs and shapes, not listed
  text "-ARM" at 3395,2550 h120 r90
  text "Cavendish" at 3278.52,2235 h160 r90
  text "RST" at 4530,1945.74 h80
Bottom Overlay:
  text "Touch" at 4674.91,3255.93 h100
  text "3V3" at 4709.26,3000 h80 r90
  text "MCU" at 4420,2935.93 h100
  text "LCD" at 3975,2015.92 h100
Top Solder:
  lines w10: 3875,3305 4070,3305 ; 3965,3405 3980,3390 ; 3980,3375 3980,3390 ; 3995,3405 3980,3390
  text "3.14" at 3940,3320.74 h80
  text "V" at 3880,3320 h90
Mechanical 15:
  lines w5: 3227.68,2008.74 3286.73,2008.74 ; 3286.73,2225.28 3286.73,2008.74 ; 3936.34,2008.74 3936.34,2076.34 3936.34,3006.34 ; 4585.94,2225.28 4585.94,2008.74 ; 4645,2008.74 4585.94,2008.74 ; 3286.73,2008.74 4585.94,2008.74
